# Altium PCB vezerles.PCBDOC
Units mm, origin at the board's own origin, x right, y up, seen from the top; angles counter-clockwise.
Board outline 152.4 x 101.6 mm, 2 copper layers (Top Layer, Bottom Layer); 54 components, 79 nets, 277 pads, 8 vias.
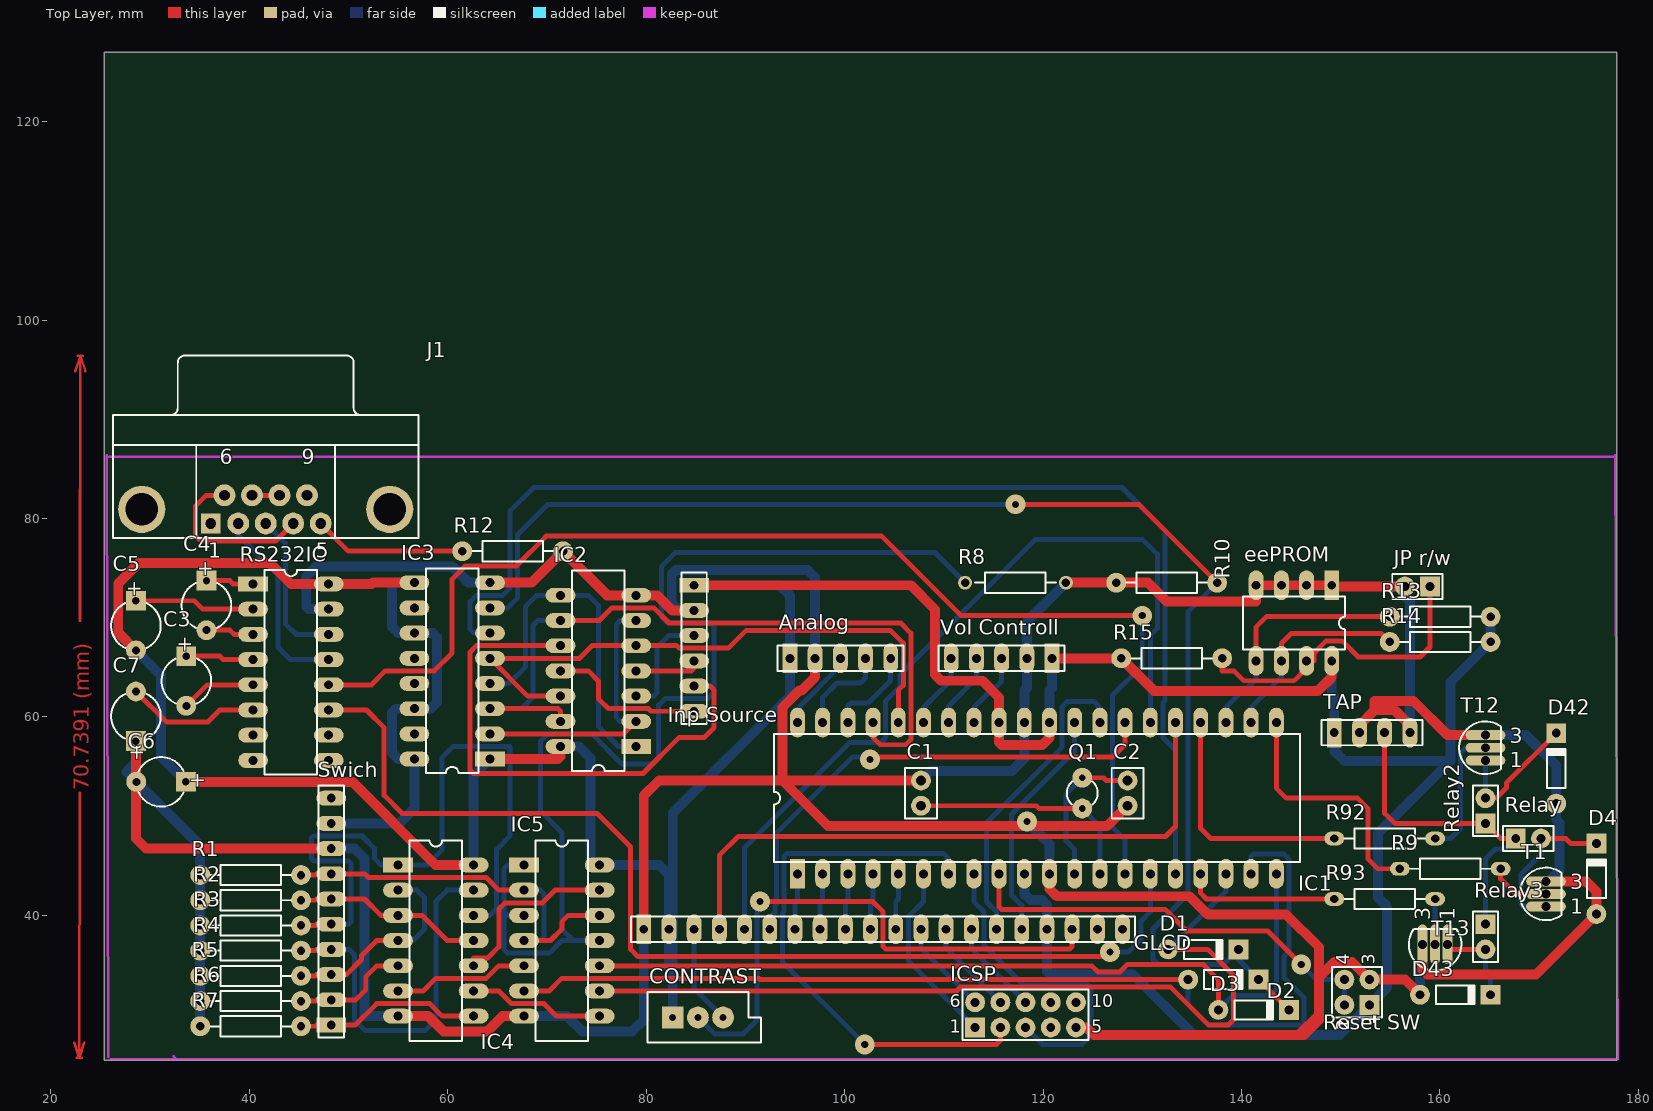
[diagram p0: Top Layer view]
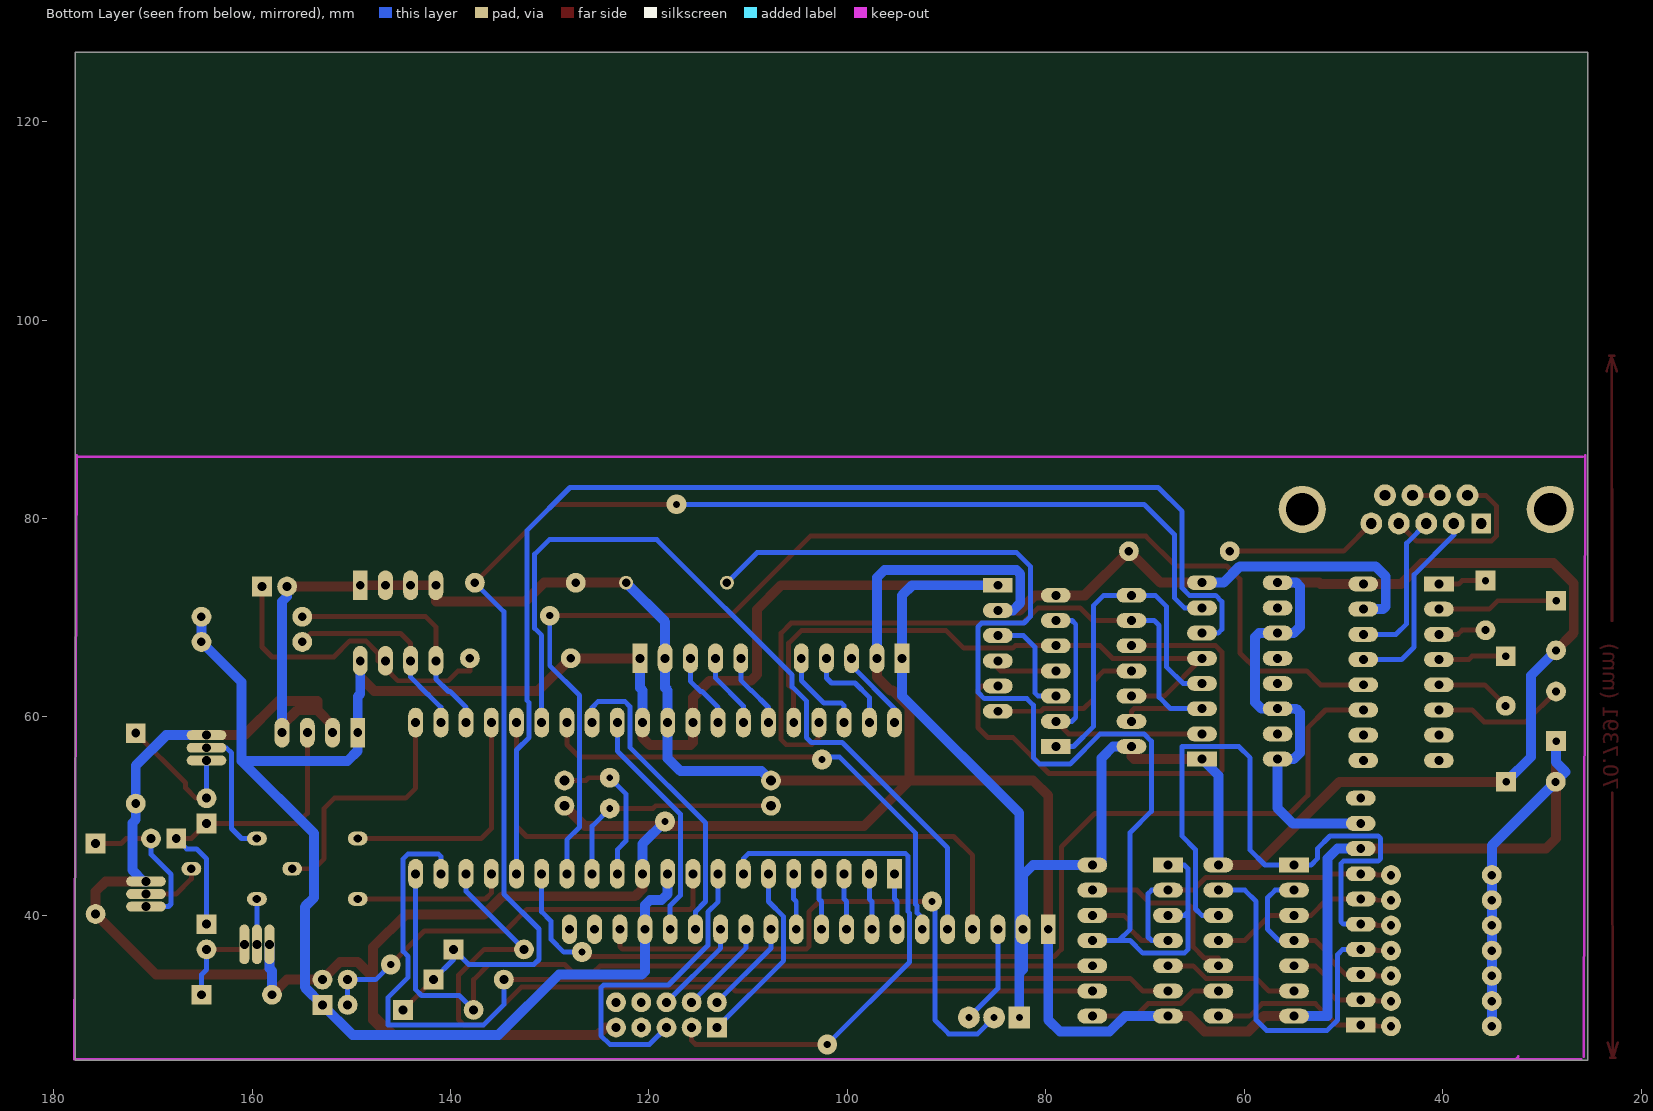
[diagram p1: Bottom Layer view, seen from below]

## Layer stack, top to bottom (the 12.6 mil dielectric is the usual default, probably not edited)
Top Layer: signal copper 0.0356
Dielectric: dielectric 0.32, FR-4, Dk 4.8
Bottom Layer: signal copper 0.0356

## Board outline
25.4,25.4 177.8,25.4 177.8,127 25.4,127

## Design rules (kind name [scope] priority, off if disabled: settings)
Clearance [All] p1: gap=0.254
ComponentClearance [All] p1: gap=0.254 collisioncheckmode=0
PolygonConnect [All] p1: connectstyle=Relief reliefconductorwidth=0.254 reliefentries=4 polygonreliefangle="90 Angle"
RoutingLayers [All] p1: top layer=Horizontal bottom layer=Vertical
RoutingTopology [All] p1: topology=Daisy_Balanced
RoutingVias [All] p1: holewidth=0.711 width=2 viastyle="Through Hole" minholewidth=0.711 minwidth=2 maxholewidth=0.711 maxwidth=2
SolderMaskExpansion [All] p1: expansion=0.102
TestPointUsage [All] p1: valid=0 allowmultiple=FALSE
Testpoint [All] p1: side=15 testpointundercomponent=TRUE minsize=1.016 maxsize=2.54 preferedsize=1.524 minholesize=0 maxholesize=1.016 preferedholesize=0.813 testpointgrid=0.025 style=1023 order=-539222988
Width Width_2 [InNet('GND')] p1: maxlimit=1 minlimit=0.254 preferedwidth=0.254 toplayer_minwidth=1 toplayer_prefwidth=1 bottomlayer_minwidth=1 bottomlayer_prefwidth=1 minimp=50.000000 maximp=50.000000 favimp=50.000000
Width Width_1 [InNet('VCC')] p2: maxlimit=1 minlimit=0.254 preferedwidth=0.254 toplayer_minwidth=1 toplayer_prefwidth=1 bottomlayer_minwidth=1 bottomlayer_prefwidth=1 minimp=50.000000 maximp=50.000000 favimp=50.000000
Width [All] p3: maxlimit=0.5 minlimit=0.254 preferedwidth=0.254 toplayer_minwidth=0.5 toplayer_prefwidth=0.5 bottomlayer_minwidth=0.5 bottomlayer_prefwidth=0.5 minimp=50.000000 maximp=50.000000 favimp=50.000000
15 further rules are at their usual default settings.

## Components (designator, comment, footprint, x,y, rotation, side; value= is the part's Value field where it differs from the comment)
Analog "Header 5" HDR1X5 94.488,65.913 r0 top
C1 "Cap" CAPR2.54-5.1X3.2 107.696,52.324 r270 top
C2 "Cap" CAPR2.54-5.1X3.2 128.524,52.324 r90 top
C3 "1uF" CAPPR5-5X5 33.655,63.627 r270 top
C4 "1uF" CAPPR5-5X5 35.687,71.247 r270 top
C5 "1uF" CAPPR5-5X5 28.575,69.215 r270 top
C6 "1uF" CAPPR5-5X5 31.115,53.467 r180 top
C7 "1uF" CAPPR5-5X5 28.575,60.071 r90 top
CONTRAST "RPot" VR5 85.217,29.718 r0 top
D1 "Diode 1N4148" DIO7.1-3.9x1.9 136.144,36.576 r0 top
D2 "Diode 1N4148" DIO7.1-3.9x1.9 138.176,33.528 r0 top
D3 "Diode 1N4148" DIO7.1-3.9x1.9 141.224,30.48 r0 top
D4 "Diode 1N4148" DIO7.1-3.9x1.9 175.768,43.688 r90 top
D42 "Diode 1N4148" DIO7.1-3.9x1.9 171.72,54.816 r90 top
D43 "Diode 1N4148" DIO7.1-3.9x1.9 161.544,32.004 r0 top
eePROM "M24C32BN1" PSDIP8A 145.288,69.469 r180 top
GLCD "Header 20" HDR1X20 79.756,38.608 r0 top
IC1 "ATmega8535-16PI" 40P6 119.38,51.816 r0 top
IC2 "HCF4081BEY" DIP14 75.184,64.643 r90 top
IC3 "HCF4009UBEY" DIP16 60.452,64.643 r90 top
IC4 "HCF4075BEY" DIP14 58.801,37.465 r270 top
IC5 "HCF4075BEY" DIP14 71.501,37.465 r270 top
ICSP "Header 5X2A" HDR2X5_CEN 113.157,28.702 r0 top
"Inp Source" "Header 6" HDR1X6 84.836,73.279 r270 top
J1 "DB-9" DSUB1.385-2H9 41.656,90.424 r0 top
"JP r/w" "Header 2" HDR1X2 159.004,73.152 r180 top
Q1 "XTAL" BCY-W2/D3.1 123.952,52.324 r180 top
R1 "Res2" AXIAL-0.4#1 40.132,44.069 r0 top
R2 "Res2" AXIAL-0.4#1 40.132,41.529 r0 top
R3 "Res2" AXIAL-0.4#1 40.132,38.989 r0 top
R4 "Res2" AXIAL-0.4#1 40.132,36.449 r0 top
R5 "Res2" AXIAL-0.4#1 40.132,33.909 r0 top
R6 "Res2" AXIAL-0.4#1 40.132,31.369 r0 top
R7 "Res2" AXIAL-0.4#1 40.132,28.829 r0 top
R8 "Res2" AXIAL-0.4#2 117.221,73.533 r180 top
R9 "Res2" AXIAL-0.4#3 161.036,44.704 r0 top
R10 "Res2" AXIAL-0.4#1 132.461,73.533 r0 top
R12 "10" AXIAL-0.4#1 66.548,76.708 r180 top
R13 "10" AXIAL-0.4#1 160.02,70.104 r0 top
R14 "10" AXIAL-0.4#1 160.02,67.564 r0 top
R15 "10" AXIAL-0.4#1 132.969,65.913 r180 top
R92 "Res2" AXIAL-0.4#3 154.432,47.752 r0 top
R93 "Res2" AXIAL-0.4#3 154.432,41.656 r0 top
Relay "Header 2" HDR1X2 167.64,47.752 r0 top
Relay2 "Header 2" HDR1X2 164.592,49.276 r90 top
Relay3 "Header 2" HDR1X2 164.592,39.116 r270 top
"Reset SW" "Header 2X2" HDR2X2 152.908,30.988 r90 top
RS232IC "MAX232" DIP16 44.196,64.516 r270 top
Swich "Header 10" HDR1X10 48.26,28.956 r90 top
T1 "NPN" BCY-W3 170.688,42.164 r0 top
T12 "NPN" BCY-W3 164.592,56.896 r0 top
T13 "NPN" BCY-W3 159.512,37.084 r90 top
TAP "Header 4" HDR1X4 149.352,58.42 r0 top
"Vol Controll" "Header 5" HDR1X5 120.904,65.913 r180 top

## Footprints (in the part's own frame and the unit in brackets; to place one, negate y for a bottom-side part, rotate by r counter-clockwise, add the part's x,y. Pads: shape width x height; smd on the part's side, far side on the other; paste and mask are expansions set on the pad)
40P6 [mm] "DIP; 40 Leads; Row Spacing 15.24 mm; Pitch 2.54 mm"
  rect 1.5x3 hole 0.9: 1(-24.13,-7.62)
  oval 1.5x3 hole 0.9: 2(-21.59,-7.62) 3(-19.05,-7.62) 4(-16.51,-7.62) 5(-13.97,-7.62) 6(-11.43,-7.62) 7(-8.89,-7.62) 8(-6.35,-7.62) 9(-3.81,-7.62) 10(-1.27,-7.62) 11(1.27,-7.62) 12(3.81,-7.62) 13(6.35,-7.62) 14(8.89,-7.62) 15(11.43,-7.62) 16(13.97,-7.62) 17(16.51,-7.62) 18(19.05,-7.62) 19(21.59,-7.62) 20(24.13,-7.62) 21(24.13,7.62) 22(21.59,7.62) 23(19.05,7.62) 24(16.51,7.62) 25(13.97,7.62) 26(11.43,7.62) 27(8.89,7.62) 28(6.35,7.62) 29(3.81,7.62) 30(1.27,7.62) 31(-1.27,7.62) 32(-3.81,7.62) 33(-6.35,7.62) 34(-8.89,7.62) 35(-11.43,7.62) 36(-13.97,7.62) 37(-16.51,7.62) 38(-19.05,7.62) 39(-21.59,7.62) 40(-24.13,7.62)
  silkscreen extent -26.5,-6.45 26.5,6.45
AXIAL-0.4#1 [mm]
  round 2 hole 0.85: 1(-5.08,0) 2(5.08,0)
  silkscreen extent -4.06,-1.02 4.06,1.02
AXIAL-0.4#2 [mm]
  round 1.4 hole 0.85: 1(-5.08,0) 2(5.08,0)
  silkscreen extent -4.06,-1.02 4.06,1.02
AXIAL-0.4#3 [mm]
  oval 2x1.4 hole 0.85: 1(-5.08,0) 2(5.08,0)
  silkscreen extent -4.06,-1.02 4.06,1.02
BCY-W2/D3.1 [mm]
  round 2 hole 0.7: 1(0,1.55) 2(0,-1.55)
  silkscreen extent -1.55,-1.19 1.55,1.17
BCY-W3 [mm]
  oval 4x1 hole 0.9: 1(0,-1.27) 2(0,0) 3(0,1.27)
  silkscreen extent -2.65,-2.65 1.55,2.65
CAPPR5-5X5 [mm]
  rect 2x2 hole 0.75: 1(-2.5,0)
  round 2 hole 0.8: 2(2.5,0)
  silkscreen extent -2.26,-2.5 2.27,2.5
CAPR2.54-5.1X3.2 [mm]
  round 2 hole 1: 1(-1.27,0) 2(1.27,0)
  silkscreen extent -2.55,-1.6 2.55,1.6
DIO7.1-3.9x1.9 [mm]
  round 2 hole 0.9: 1(-3.55,0)
  rect 2x2 hole 0.9: 2(3.55,0)
  silkscreen extent -1.95,-0.95 2.05,0.95
DIP14 [mm] "DIP; 14 Leads; Row Spacing 7.62 mm; Pitch 2.54 mm"
  rect 1.5x3 hole 0.9: 1(-7.62,-3.81)
  oval 1.5x3 hole 0.9: 2(-5.08,-3.81) 3(-2.54,-3.81) 4(0,-3.81) 5(2.54,-3.81) 6(5.08,-3.81) 7(7.62,-3.81) 8(7.62,3.81) 9(5.08,3.81) 10(2.54,3.81) 11(0,3.81) 12(-2.54,3.81) 13(-5.08,3.81) 14(-7.62,3.81)
  silkscreen extent -10.1,-2.65 10.1,2.65
DIP16 [mm] "DIP; 16 Leads; Row Spacing 7.62 mm; Pitch 2.54 mm"
  rect 1.5x3 hole 0.9: 1(-8.89,-3.81)
  oval 1.5x3 hole 0.9: 2(-6.35,-3.81) 3(-3.81,-3.81) 4(-1.27,-3.81) 5(1.27,-3.81) 6(3.81,-3.81) 7(6.35,-3.81) 8(8.89,-3.81) 9(8.89,3.81) 10(6.35,3.81) 11(3.81,3.81) 12(1.27,3.81) 13(-1.27,3.81) 14(-3.81,3.81) 15(-6.35,3.81) 16(-8.89,3.81)
  silkscreen extent -10.3,-2.65 10.3,2.65
DSUB1.385-2H9 [mm] "Connector; D Subminiature; 9 Position; Right Angle; Pitch 1.385 mm"
  rect 2x2 hole 1.09: 1(-5.54,-10.92)
  round 2.2 hole 1.09: 2(-2.77,-10.92) 3(0,-10.92) 4(2.77,-10.92) 5(5.54,-10.92) 6(-4.155,-8.08) 7(-1.385,-8.08) 8(1.385,-8.08) 9(4.155,-8.08)
  round 4.76 hole 3.26: 10(-12.495,-9.5) 11(12.495,-9.5)
  silkscreen extent -15.4,-12.4 15.4,6
HDR1X2 [mm] "Connector; Header; 2 Position"
  rect 2x2 hole 0.9: 1(0,0)
  round 2 hole 0.9: 2(2.54,0)
  silkscreen extent -1.27,-1.27 3.81,1.27
HDR1X4 [mm] "Connector; Header; 4 Position"
  rect 1.5x3 hole 0.9: 1(0,0)
  oval 1.5x3 hole 0.9: 2(2.54,0) 3(5.08,0) 4(7.62,0)
  silkscreen extent -1.27,-1.27 8.89,1.27
HDR1X5 [mm] "Connector; Header; 5 Position"
  rect 1.5x3 hole 0.9: 1(0,0)
  oval 1.5x3 hole 0.9: 2(2.54,0) 3(5.08,0) 4(7.62,0) 5(10.16,0)
  silkscreen extent -1.27,-1.27 11.43,1.27
HDR1X6 [mm] "Connector; Header; 6 Position"
  rect 1.5x3 hole 0.9: 1(0,0)
  oval 1.5x3 hole 0.9: 2(2.54,0) 3(5.08,0) 4(7.62,0) 5(10.16,0) 6(12.7,0)
  silkscreen extent -1.27,-1.27 13.97,1.27
HDR1X10 [mm] "Connector; Header; 10 Position"
  rect 1.5x3 hole 0.9: 1(0,0)
  oval 1.5x3 hole 0.9: 2(2.54,0) 3(5.08,0) 4(7.62,0) 5(10.16,0) 6(12.7,0) 7(15.24,0) 8(17.78,0) 9(20.32,0) 10(22.86,0)
  silkscreen extent -1.27,-1.27 24.13,1.27
HDR1X20 [mm] "Connector; Header; 20 Position"
  rect 1.5x3 hole 0.9 paste+0: 1(0,0)
  oval 1.5x3 hole 0.9 paste+0: 2(2.54,0) 3(5.08,0) 4(7.62,0) 5(10.16,0) 6(12.7,0) 7(15.24,0) 8(17.78,0) 9(20.32,0) 10(22.86,0) 11(25.4,0) 12(27.94,0) 13(30.48,0) 14(33.02,0) 15(35.56,0) 16(38.1,0) 17(40.64,0) 18(43.18,0) 19(45.72,0) 20(48.26,0)
  silkscreen extent -1.27,-1.27 49.53,1.27
HDR2X2 [mm] "Connector; Header; 2x2 Position"
  rect 2x2 hole 0.9: 1(0,0)
  round 2 hole 0.9: 2(0,2.54) 3(2.54,0) 4(2.54,2.54)
  silkscreen extent -1.27,-1.27 3.81,3.81
HDR2X5_CEN [mm] "Connector; Header; 5x2 Position"
  rect 2x2 hole 0.9: 1(0,0)
  round 2 hole 0.9: 2(2.54,0) 3(5.08,0) 4(7.62,0) 5(10.16,0) 6(0,2.54) 7(2.54,2.54) 8(5.08,2.54) 9(7.62,2.54) 10(10.16,2.54)
  silkscreen extent -1.27,-1.27 11.43,3.81
PSDIP8A [mm] "DIP; 8 Leads; Row Spacing 7.62 mm; Pitch 2.54 mm"
  rect 1.5x3 hole 0.9: 1(-3.81,-3.81)
  oval 1.5x3 hole 0.9: 2(-1.27,-3.81) 3(1.27,-3.81) 4(3.81,-3.81) 5(3.81,3.81) 6(1.27,3.81) 7(-1.27,3.81) 8(-3.81,3.81)
  silkscreen extent -5.15,-2.65 5.15,2.65
VR5 [mm]
  rect 2.2x2.2 hole 0.7: 1(-2.54,0)
  round 2.2 hole 0.7: 2(0,0) 3(2.54,0)
  silkscreen extent -5.08,-2.54 6.35,2.54

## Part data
Analog "Vol Controll": "Header, 5-Pin"
C1 C2: "Capacitor"
C3 C4 C5 C6 C7: library part CPOL, "Elektrolit kondenzátor"
CONTRAST: "Potentiometer"
D1 D2 D3 D4 D42 D43: "High Conductance Fast Diode"
eePROM: "32 Kbit Serial I²C Bus EEPROM"
GLCD: "Header, 20-Pin"
IC1: "8-Bit AVR Microcontroller with 8K Bytes of In-System Programmable Flash Memory"
IC2: "Quad 2-Input AND Gate"
IC3: "Hex Buffer/Converter"
IC4 IC5: "Triple 3-Input OR Gate"
ICSP: "Header, 5-Pin, Dual row"
"Inp Source": "Header, 6-Pin"
J1: library part DB9
"JP r/w" Relay Relay2 Relay3: "Header, 2-Pin"
Q1: "Crystal Oscillator"
R1 R2 R3 R4 R5 R6 R7 R8 R9 R10 R92 R93: "Resistor"
R12 R13 R14 R15: library part Res2, "Resistor"
"Reset SW": "Header, 2-Pin, Dual row"
RS232IC: "DUAL EIA-232 DRIVER/RECEIVER"
Swich: "Header, 10-Pin"
T1 T12 T13: "NPN Bipolar Transistor"
TAP: "Header, 4-Pin"

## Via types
v1: diameter 2, hole 0.711, Top Layer to Bottom Layer, 8 vias

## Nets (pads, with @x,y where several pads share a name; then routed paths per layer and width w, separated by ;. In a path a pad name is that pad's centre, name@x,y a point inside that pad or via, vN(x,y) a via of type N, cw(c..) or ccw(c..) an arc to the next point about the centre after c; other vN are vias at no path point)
12: Relay2.1 Relay3.1 Relay.1 TAP.3 | length 32.9
  Top Layer w0.5: TAP.3 154.432,50.292 155.448,49.276 Relay2.1 166.116,47.752 Relay.1
  Bottom Layer w0.5: Relay3.1 164.592,45.695 165.608,46.711 166.599,46.711 Relay.1
+10V: C5.1 RS232IC.2 | length 12.2
  Top Layer w0.5: C5.1 34.468,71.715 35.317,70.866 RS232IC.2
-10V: C7.2 RS232IC.6 | length 13.6
  Top Layer w0.5: C7.2 31.634,59.512 35.839,59.512 37.033,60.706 RS232IC.6
CS1: GLCD.15 IC1.28 | length 31.8
  Bottom Layer w0.5: GLCD.15 115.316,40.386 114.3,41.402 114.3,49.327 121.92,56.947 121.92,61.062 122.428,61.57 125.12,61.57 125.73,60.96 IC1.28
CS2: GLCD.16 IC1.29 | length 23.9
  Bottom Layer w0.5: GLCD.16 117.856,40.996 116.84,42.012 116.84,50.216 123.19,56.566 IC1.29
D0: GLCD.7 IC1.1 | length 5.7
  Bottom Layer w0.5: GLCD.7 94.996,41.402 95.25,41.656 IC1.1
D1: GLCD.8 IC1.2 | length 5.7
  Bottom Layer w0.5: GLCD.8 97.536,41.402 97.79,41.656 IC1.2
D2: GLCD.9 IC1.3 | length 5.7
  Bottom Layer w0.5: GLCD.9 100.076,41.402 100.33,41.656 IC1.3
D3: GLCD.10 IC1.4 | length 5.7
  Bottom Layer w0.5: GLCD.10 102.616,41.402 102.87,41.656 IC1.4
D4: GLCD.11 IC1.5 | length 5.7
  Bottom Layer w0.5: GLCD.11 105.156,41.402 105.41,41.656 IC1.5
D5: GLCD.12 ICSP.6 | length 9.6
  Bottom Layer w0.5: GLCD.12 107.696,36.703 ICSP.6
D6: GLCD.13 ICSP.7 | length 9.6
  Bottom Layer w0.5: GLCD.13 110.236,36.703 ICSP.7
D7: GLCD.14 ICSP.8 | length 9.6
  Bottom Layer w0.5: GLCD.14 112.776,36.703 ICSP.8
E: GLCD.6 IC1.27 | length 51.2
  Top Layer w0.5: v1(102.565,55.702) 102.819,55.956 127,55.956 128.27,57.226 IC1.27
  Bottom Layer w0.5: GLCD.6 92.456,39.751 92.964,40.259 92.964,40.97 93.116,41.123 93.116,48.285 100.787,55.956 102.311,55.956 v1(102.565,55.702)
GND: "Inp Source.2" "JP r/w.2" "Reset SW.3" "Vol Controll.2" Analog.2 C1.1 C2.1 C6.2 C7.1 D4.1 D42.1 D43.1 eePROM.1 eePROM.2 eePROM.3 eePROM.4 GLCD.1 IC1.11 IC1.31 IC2.7 IC3.8 IC4.7 IC5.7 ICSP.5 R1.1 R2.1 R3.1 R4.1 R5.1 R6.1 R7.1 R8.1 R10.1 R12.1 RS232IC.15 Swich.8 T1.3 T12.3 T13.3 TAP.2 TAP.4 | length 539.1
  Top Layer w1: C7.1 28.575,53.467 28.575,47.752 29.591,46.736 Swich.8 ; IC4.7 58.039,29.845 59.563,28.321 64.008,28.321 65.532,29.845 IC5.7 ; IC3.8 68.453,73.533 R12.1 76.073,72.263 IC2.7 81.102,72.263 82.626,70.739 84.836,70.739 ; GLCD.1 79.756,52.07 81.28,53.594 93.726,53.594 ; Analog.2 97.028,64.008 95.682,62.662 95.428,62.662 93.726,60.96 93.726,53.594 ; C1.1 93.726,53.594 ; v1(118.389,49.479) v1@118.872,48.997 ; IC1.11 120.65,42.672 121.387,41.935 134.772,41.935 136.601,40.107 144.501,40.107 147.803,36.805 147.803,33.757 ; R8.1 R10.1 130.581,73.533 132.461,71.653 141.478,71.653 eePROM.4 eePROM.3 eePROM.2 eePROM.1 149.098,73.152 156.464,73.152 ; ICSP.5 124.384,28.702 125.12,27.965 145.796,27.965 ; C2.1 126.467,48.997 v1@118.872,48.997 ; TAP.2 151.892,59.157 153.416,60.681 ; TAP.4 156.972,59.157 155.448,60.681 153.416,60.681 ; D43.1 156.47,33.528 152.908,33.528 151.13,35.306 149.352,35.306 147.803,33.757 ; T13.3 158.242,34.544 158.75,34.036 169.666,34.036 D4.1 175.768,42.418 174.752,43.434 T1.3 ; T12.3 160.782,58.166 157.328,61.62 153.416,61.62 153.416,60.681 ; 93.726,53.594 98.323,48.997 118.389,48.997 v1@118.872,48.997 ; 145.796,27.965 147.803,29.972 ; 145.796,27.965 146.304,27.965 147.803,29.464 147.803,29.972 ; 147.803,29.972 147.803,33.757
  Bottom Layer w1: C7.1 28.575,55.437 27.61,54.472 C6.2 35.052,47.03 R1.1 R2.1 R3.1 R4.1 R5.1 R6.1 R7.1 ; RS232IC.15 45.999,70.866 45.745,71.12 45.745,74.168 46.761,75.184 60.452,75.184 62.103,73.533 IC3.8 ; Swich.8 50.597,46.736 51.613,45.72 51.613,29.87 51.638,29.845 IC4.7 ; IC5.7 72.034,29.845 73.584,28.296 78.588,28.296 79.756,29.464 GLCD.1 ; 84.836,70.739 83.312,70.739 82.575,71.476 82.575,74.422 82.956,74.803 96.266,74.803 97.028,74.041 Analog.2 ; C1.1 108.661,54.559 116.84,54.559 118.11,55.829 IC1.31 118.11,62.687 118.364,62.941 118.364,65.913 118.364,69.596 R8.1 ; v1(118.389,49.479) 120.65,47.219 IC1.11 ; 156.464,73.152 156.464,72.136 156.972,71.628 TAP.4 ; D43.1 157.994,34.417 158.242,34.665 T13.3 ; T12.3 168.656,58.166 171.72,55.102 D42.1 171.72,49.666 172.06,49.327 172.06,44.552 170.942,43.434 T1.3
NetAnalog_3: Analog.3 IC1.40 | length 8.3
  Bottom Layer w0.5: IC1.40 95.25,60.833 99.568,65.151 Analog.3
NetAnalog_4: Analog.4 IC1.39 | length 9.6
  Bottom Layer w0.5: IC1.39 97.79,61.976 99.238,63.424 101.6,63.424 102.108,63.932 Analog.4
NetAnalog_5: Analog.5 IC1.38 | length 9.3
  Bottom Layer w0.5: IC1.38 100.33,61.138 100.584,61.392 102.362,61.392 104.648,63.678 Analog.5
NetC1_2: C1.2 IC1.13 Q1.1 | length 23.7
  Top Layer w0.5: C1.2 119.329,51.054 119.609,50.774 Q1.1
  Bottom Layer w0.5: Q1.1 125.73,48.996 IC1.13
NetC2_2: C2.2 IC1.12 Q1.2 | length 15.4
  Top Layer w0.5: Q1.2 126.086,53.874 126.366,53.594 C2.2
  Bottom Layer w0.5: IC1.12 123.19,46.634 122.326,47.498 122.326,52.248 Q1.2
NetC3_1: C3.1 RS232IC.4 | length 6.9
  Top Layer w0.5: C3.1 37.033,66.127 37.374,65.786 RS232IC.4
NetC3_2: C3.2 RS232IC.5 | length 7.6
  Top Layer w0.5: C3.2 35.774,63.246 RS232IC.5
NetC4_1: C4.1 RS232IC.1 | length 4.8
  Top Layer w0.5: C4.1 38.049,73.747 38.39,73.406 RS232IC.1
NetC4_2: C4.2 RS232IC.3 | length 4.9
  Top Layer w0.5: C4.2 38.049,68.747 38.47,68.326 RS232IC.3
NetD1_1: D1.1 IC1.18 IC5.9 | length 88
  Top Layer w0.5: IC5.9 111.277,32.385 111.658,32.766 132.862,32.766 136.652,28.976 138.684,28.976 139.192,29.484 139.192,33.985 136.601,36.576 D1.1
  Bottom Layer w0.5: D1.1 138.43,42.412 IC1.18
NetD1_2: D1.2 D2.2 D3.2 IC3.7 R10.2 | length 142.9
  Top Layer w0.5: v1(117.221,81.432) 129.642,81.432 R10.2 ; D2.2 141.726,33.509 144.755,30.48 D3.2
  Bottom Layer w0.5: IC3.7 66.04,70.993 67.056,72.009 67.056,78.384 70.104,81.432 v1(117.221,81.432) ; R10.2 134.62,70.612 134.62,42.164 131.089,38.633 131.089,35.56 131.597,35.052 138.17,35.052 D1.2 139.694,35.56 D2.2
NetD2_1: D2.1 IC1.19 IC5.6 | length 106.2
  Top Layer w0.5: IC5.6 70.231,32.385 71.501,33.655 91.364,33.655 91.491,33.528 D2.1
  Bottom Layer w0.5: D2.1 134.626,31.002 136.652,28.976 146.279,28.976 146.279,31.75 144.272,33.757 144.272,35.865 144.78,36.373 144.78,45.695 144.272,46.203 141.224,46.203 140.97,45.949 IC1.19
NetD3_1: D3.1 IC1.20 IC5.10 | length 85
  Top Layer w0.5: IC5.10 124.917,34.925 125.552,34.29 127.737,34.29 128.499,35.052 136.15,35.052 137.674,33.528 D3.1
  Bottom Layer w0.5: D3.1 139.122,31.928 142.926,31.928 143.51,32.512 IC1.20
NetD4_2: D4.2 Relay.2 T1.1 | length 15.9
  Top Layer w0.5: Relay.2 172.695,47.752 173.209,47.238 D4.2
  Bottom Layer w0.5: Relay.2 170.18,46.152 168.173,44.145 168.173,41.148 168.427,40.894 T1.1
NetD42_2: D42.2 Relay2.2 T12.1 | length 13.9
  Top Layer w0.5: Relay2.2 165.678,51.816 166.7,52.838 166.7,53.346 D42.2
  Bottom Layer w0.5: Relay2.2 T12.1
NetD43_2: D43.2 Relay3.2 T13.1 | length 9.1
  Top Layer w0.5: T13.1 160.782,36.576 Relay3.2
  Bottom Layer w0.5: Relay3.2 164.592,34.538 165.094,34.036 D43.2
Neteeprom_5: eePROM.5 IC1.23 R13.1 | length 24.9
  Top Layer w0.5: eePROM.5 141.478,69.088 142.494,70.104 R13.1
  Bottom Layer w0.5: IC1.23 138.43,60.96 140.03,62.56 140.208,62.56 141.478,63.83 eePROM.5
Neteeprom_6: eePROM.6 IC1.22 R14.1 | length 21
  Top Layer w0.5: eePROM.6 144.018,67.412 145.034,68.428 154.076,68.428 R14.1
  Bottom Layer w0.5: IC1.22 140.97,60.985 142.24,62.255 142.265,62.255 144.018,64.008 eePROM.6
Neteeprom_7: "JP r/w.1" eePROM.7 R15.1 | length 32.4
  Top Layer w0.5: R15.1 138.049,64.618 139.271,64.618 140.236,63.652 145.313,63.652 146.558,64.897 eePROM.7 147.32,65.659 147.32,66.446 148.539,67.666 150.139,67.666 151.765,66.04 157.988,66.04 159.004,67.056 159.004,73.152
NetIC1_9: "Reset SW.2" "Reset SW.4" IC1.9 | length 43.7
  Top Layer w0.5: IC1.9 115.57,40.869 115.824,40.615 132.309,40.615 134.493,38.43 142.646,38.43 v1(146.025,35.052)
  Bottom Layer w0.5: v1(146.025,35.052) 147.549,33.528 150.368,33.528 150.368,30.988
NetIC1_16: IC1.16 IC3.6 | length 121.3
  Bottom Layer w0.5: IC3.6 62.636,68.453 62.255,68.834 62.255,71.628 62.89,72.263 65.532,72.263 66.269,73 66.269,80.721 68.682,83.134 127.965,83.134 132.283,78.816 132.283,61.646 132.08,61.443 132.08,57.937 133.35,56.667 IC1.16
NetIC1_17: IC1.17 R93.1 | length 15.7
  Top Layer w0.5: IC1.17 135.89,42.24 136.474,41.656 R93.1
NetIC1_21: IC1.21 R9.1 | length 25.4
  Top Layer w0.5: IC1.21 143.51,52.832 144.526,51.816 151.714,51.816 152.73,50.8 152.73,45.72 153.746,44.704 R9.1
NetIC1_24: IC1.24 R92.1 | length 24.6
  Top Layer w0.5: IC1.24 135.89,48.768 136.906,47.752 R92.1
NetIC1_33: "Vol Controll.3" IC1.33 | length 7.7
  Bottom Layer w0.5: IC1.33 113.03,60.96 114.656,62.586 114.808,62.586 115.824,63.602 115.824,65.913
NetIC1_34: "Vol Controll.4" IC1.34 | length 7.6
  Bottom Layer w0.5: IC1.34 110.49,61.112 113.284,63.906 113.284,65.913
NetIC1_35: "Vol Controll.5" IC1.35 | length 7.7
  Bottom Layer w0.5: IC1.35 107.95,60.96 109.677,62.687 109.728,62.687 110.744,63.703 110.744,65.913
NetIC1_36: IC1.36 IC2.5 IC2.12 IC3.5 | length 60.5
  Top Layer w0.5: IC2.12 68.072,62.103 IC3.5 73.279,65.913 74.549,67.183 IC2.5 83.083,67.183 83.337,66.929 88.265,66.929 90.043,68.707 104.648,68.707 105.918,67.437 105.918,63.195 105.41,62.687 IC1.36
NetIC1_37: IC1.37 IC2.9 IC2.13 IC3.3 | length 76.7
  Top Layer w0.5: IC3.3 71.12,60.833 71.374,60.579 IC2.13 ; IC2.9 75.286,69.723 76.556,70.993 80.772,70.993 82.296,69.469 105.664,69.469 106.68,68.453 106.68,57.709 106.172,57.201 103.581,57.201 102.87,57.912 IC1.37
  Bottom Layer w0.5: IC3.3 67.437,60.833 68.58,61.976 68.58,69.215 69.088,69.723 IC2.9
NetIC2_1: IC2.1 IC2.8 IC3.4 | length 35.4
  Bottom Layer w0.5: IC3.4 66.167,63.373 67.818,65.024 67.818,71.12 68.961,72.263 IC2.8 74.168,72.263 75.184,71.247 75.184,59.055 77.216,57.023 IC2.1
NetIC2_2: IC2.2 IC2.6 IC3.2 | length 29
  Top Layer w0.5: IC3.2 77.724,58.293 IC2.2
  Bottom Layer w0.5: IC2.2 77.368,59.563 76.987,59.944 76.987,69.342 77.368,69.723 IC2.6
NetIC2_3: "Inp Source.3" IC2.3 | length 11.1
  Bottom Layer w0.5: IC2.3 80.772,62.103 81.102,62.433 81.102,67.056 82.245,68.199 84.836,68.199
NetIC2_4: "Inp Source.4" IC2.4 | length 6.7
  Top Layer w0.5: IC2.4 84.582,64.643 84.836,64.897 84.836,65.659
NetIC2_10: "Inp Source.5" IC2.10 | length 53.9
  Top Layer w0.5: IC2.10 62.89,67.183 62.255,66.548 62.255,54.61 62.56,54.305 79.68,54.305 83.287,57.912 85.827,57.912 86.843,58.928 86.843,62.738 86.462,63.119 84.836,63.119
NetIC2_11: "Inp Source.6" IC2.11 | length 16.2
  Top Layer w0.5: IC2.11 74.168,64.643 75.184,63.627 75.184,61.849 76.2,60.833 80.239,60.833 80.493,60.579 84.836,60.579
NetIC4_1: IC4.1 IC4.12 R3.2 Swich.5 | length 69.1
  Top Layer w0.5: R3.2 46.66,38.989 46.787,39.116 Swich.5
  Bottom Layer w0.5: Swich.5 50.013,39.116 50.267,39.37 50.267,45.212 50.013,45.466 46.507,45.466 46.253,45.72 46.253,47.752 46.507,48.006 51.359,48.006 52.629,46.736 52.629,45.72 53.264,45.085 IC4.1 57.912,45.085 59.411,46.584 59.411,55.88 60.554,57.023 66.269,57.023 66.269,47.981 64.922,46.634 64.922,40.64 64.287,40.005 IC4.12
NetIC4_2: IC4.2 IC4.4 R5.2 Swich.3 | length 20.8
  Top Layer w0.5: R5.2 46.66,33.909 46.787,34.036 Swich.3 49.784,34.036 51.308,35.56 51.308,35.941 52.832,37.465 IC4.4
  Bottom Layer w0.5: IC4.4 56.515,37.465 57.658,38.608 57.658,41.783 56.896,42.545 IC4.2
NetIC4_3: IC4.3 IC4.11 R2.2 Swich.6 | length 19.2
  Top Layer w0.5: R2.2 46.66,41.529 46.787,41.656 Swich.6 51.613,41.656 53.264,40.005 IC4.3 57.404,40.005 59.944,37.465 IC4.11
NetIC4_5: IC4.5 R6.2 Swich.2 | length 12
  Top Layer w0.5: R6.2 46.66,31.369 46.787,31.496 Swich.2 50.724,31.496 51.74,32.512 51.74,33.833 52.832,34.925 IC4.5
NetIC4_6: IC4.6 IC5.5 | length 13.8
  Top Layer w0.5: IC4.6 57.531,32.385 58.801,33.655 63.881,33.655 65.151,34.925 IC5.5
NetIC4_8: IC4.8 R7.2 Swich.1 | length 18.9
  Top Layer w0.5: R7.2 46.66,28.829 46.787,28.956 Swich.1 50.673,28.956 52.832,31.115 58.191,31.115 59.461,29.845 IC4.8
NetIC4_9: IC4.9 IC5.8 | length 13.8
  Top Layer w0.5: IC4.9 65.151,32.385 66.421,31.115 69.698,31.115 70.968,29.845 IC5.8
NetIC4_10: IC4.10 IC5.13 | length 18.5
  Top Layer w0.5: IC4.10 62.611,35.687 64.008,35.687 65.151,36.83 65.151,40.64 65.786,41.275 69.545,41.275 70.815,42.545 IC5.13
NetIC4_13: IC4.13 R4.2 Swich.4 | length 37.5
  Top Layer w0.5: R4.2 46.66,36.449 46.787,36.576 Swich.4
  Bottom Layer w0.5: Swich.4 50.089,36.576 50.597,36.068 50.597,29.464 51.638,28.423 57.76,28.423 58.801,29.464 58.801,41.402 59.944,42.545 IC4.13
NetIC5_1: IC5.1 IC5.3 IC5.11 R8.2 | length 119.2
  Bottom Layer w0.5: IC5.3 66.04,40.005 65.684,40.361 ; IC5.1 66.04,45.085 65.684,44.729 65.684,40.361 ; IC5.11 72.644,37.465 ; R8.2 109.118,76.556 82.931,76.556 81.559,75.184 81.559,70.104 82.194,69.469 86.462,69.469 86.843,69.088 86.843,62.484 86.208,61.849 81.915,61.849 81.255,61.189 81.255,55.88 80.62,55.245 77.572,55.245 74.524,58.293 70.104,58.293 69.367,57.556 69.367,50.495 71.501,48.362 71.501,38.608 72.644,37.465 ; 65.684,40.361 65.684,36.551 66.04,36.195 70.231,36.195 71.501,37.465 72.644,37.465
NetIC5_2: IC5.2 IC5.4 IC5.12 R1.2 Swich.7 | length 41
  Top Layer w0.5: R1.2 46.66,44.069 46.787,44.196 Swich.7 51.638,44.196 52.019,43.815 63.881,43.815 65.151,42.545 IC5.2 ; IC5.4 70.358,37.465 71.501,38.608 71.501,39.37 72.136,40.005 IC5.12
  Bottom Layer w0.5: IC5.4 69.342,37.465 69.698,37.821 69.698,42.189 69.342,42.545 IC5.2
NetJ1_2: J1.2 RS232IC.13 | length 19.8
  Bottom Layer w0.5: J1.2 38.886,78.335 42.875,74.346 42.875,67.056 44.145,65.786 RS232IC.13
NetJ1_3: J1.3 RS232IC.14 | length 15.7
  Bottom Layer w0.5: J1.3 43.637,77.523 43.637,69.393 44.704,68.326 RS232IC.14
NetJ1_4: J1.4 J1.6 | length 17.2
  Top Layer w0.5: J1.6 35.659,82.344 34.595,81.28 34.595,78.232 35.103,77.724 42.646,77.724 J1.4
NetJ1_5: J1.5 R12.2 | length 15.4
  Top Layer w0.5: J1.5 49.992,76.708 R12.2
NetJ1_7: J1.7 J1.8 | length 2.8
  Top Layer w0.5: J1.7 J1.8
NetR9_2: R9.2 T1.2 | length 6.2
  Top Layer w0.5: R9.2 166.116,43.688 167.64,42.164 T1.2
NetR92_2: R92.2 T12.2 | length 13.3
  Bottom Layer w0.5: R92.2 161.061,47.752 162.077,48.768 162.077,56.388 162.585,56.896 T12.2
NetR93_2: R93.2 T13.2 | length 4.6
  Bottom Layer w0.5: T13.2 R93.2
PB5: IC1.6 ICSP.1 | length 18.9
  Bottom Layer w0.5: IC1.6 107.95,41.402 106.426,39.878 106.426,35.433 ICSP.1
PB6: IC1.7 ICSP.2 | length 56.1
  Top Layer w0.5: v1(102.032,27) 115.316,27 115.697,27.381 ICSP.2
  Bottom Layer w0.5: v1(102.032,27) 93.726,35.306 93.726,40.234 93.878,40.386 93.878,45.974 94.158,46.253 109.957,46.253 110.49,45.72 IC1.7
PB7: IC1.8 ICSP.3 | length 32.7
  Bottom Layer w0.5: IC1.8 113.03,41.377 114.046,40.361 114.046,36.982 118.034,32.995 124.562,32.995 124.841,32.715 124.841,27.889 123.952,27 119.939,27 ICSP.3
RS: GLCD.4 IC1.25 | length 65.1
  Top Layer w0.5: GLCD.4 87.376,46.05 89.281,47.955 132.334,47.955 133.35,48.971 IC1.25
RW: GLCD.5 IC1.26 | length 83.4
  Bottom Layer w0.5: GLCD.5 89.916,46.812 100.533,57.429 103.632,57.429 104.14,57.937 104.14,61.62 105.562,63.043 105.562,64.237 119.202,77.876 130.048,77.876 131.521,76.403 131.521,68.936 130.81,68.224 IC1.26
RXD: IC1.14 RS232IC.12 | length 123.7
  Top Layer w0.5: RS232IC.12 52.324,63.246 53.721,64.643 58.649,64.643 60.452,66.446 60.452,73.889 61.773,75.209 66.904,75.209 69.926,78.232 103.734,78.232 111.76,70.206 v1(129.997,70.206)
  Bottom Layer w0.5: IC1.14 128.27,47.625 127,48.895 127,62.179 129.997,65.176 v1(129.997,70.206)
TXD: IC1.15 RS232IC.11 | length 109.9
  Top Layer w0.5: RS232IC.11 51.816,60.706 53.594,58.928 53.594,52.095 55.423,50.267 75.057,50.267 78.435,46.888 78.435,36.576 79.172,35.839 126.289,35.839 v1(126.746,36.297)
  Bottom Layer w0.5: v1(126.746,36.297) 128.575,36.297 129.87,37.592 129.87,39.421 130.81,40.361 IC1.15
V0: CONTRAST.3 GLCD.3 | length 10.1
  Bottom Layer w0.5: GLCD.3 84.836,32.639 CONTRAST.3
VCC: "Inp Source.1" "Reset SW.1" "Vol Controll.1" Analog.1 C5.2 C6.1 CONTRAST.1 eePROM.8 GLCD.2 GLCD.17 IC1.10 IC1.30 IC1.32 IC2.14 IC3.1 IC3.9 IC3.11 IC3.14 IC3.16 IC4.14 IC5.14 R13.2 R14.2 R15.2 RS232IC.16 Swich.9 TAP.1 | length 443.5
  Top Layer w1: C5.2 26.797,68.493 26.797,73.457 28.854,75.514 42.088,75.514 44.196,73.406 RS232IC.16 52.324,73.406 52.451,73.533 IC3.9 ; C6.1 50.394,53.467 58.776,45.085 IC4.14 ; IC3.1 71.12,55.753 71.374,56.007 IC2.14 ; 84.836,73.279 106.68,73.279 109.118,70.841 109.118,64.262 109.728,63.652 113.894,63.652 115.57,61.976 IC1.32 115.57,57.429 115.824,57.175 119.913,57.175 120.65,57.912 IC1.30 ; 120.904,65.913 R15.2 131.166,62.636 147.726,62.636 149.098,64.008 eePROM.8
  Bottom Layer w1: C5.2 31.115,64.175 31.115,55.967 C6.1 ; Swich.9 55.118,49.276 56.642,50.8 IC3.16 55.016,55.753 54.381,56.388 54.381,60.452 54.762,60.833 IC3.14 58.268,60.833 58.903,61.468 58.903,68.072 58.522,68.453 IC3.11 55.016,68.453 54.381,69.088 54.381,73.152 54.762,73.533 IC3.9 ; IC4.14 62.611,54.102 IC3.1 ; IC2.14 73.228,57.023 74.371,55.88 74.371,45.085 IC5.14 81.28,45.085 82.296,44.069 GLCD.2 82.296,34.544 82.677,34.163 ; CONTRAST.1 82.677,34.163 ; 84.836,73.279 93.472,73.279 94.488,72.263 Analog.1 94.488,62.128 82.677,50.317 82.677,38.608 82.677,34.163 ; IC1.10 118.11,42.164 118.72,41.554 119.888,41.554 120.396,41.046 GLCD.17 120.396,34.366 120.726,34.036 129.083,34.036 135.153,27.965 149.885,27.965 152.908,30.988 154.686,32.766 154.686,40.869 153.772,41.783 153.772,48.285 161.061,55.575 ; IC1.30 120.65,62.687 120.904,62.941 120.904,65.913 ; eePROM.8 149.098,62.306 149.352,62.052 TAP.1 149.352,56.591 150.368,55.575 161.061,55.575 ; R13.2 R14.2 161.061,63.525 161.061,55.575
VOUT: CONTRAST.2 GLCD.18 | length 56.7
  Top Layer w0.5: v1(91.465,41.402) 102.845,41.402 103.886,40.361 103.886,36.855 104.14,36.601 122.682,36.601 122.936,36.855 GLCD.18
  Bottom Layer w0.5: CONTRAST.2 86.868,28.067 89.789,28.067 91.186,29.464 91.186,41.123 v1(91.465,41.402)
pads on no net: GLCD.19 GLCD.20 IC3.10 IC3.12 IC3.13 IC3.15 ICSP.4 ICSP.9 ICSP.10 J1.1 J1.9 J1.10 J1.11 RS232IC.7 RS232IC.8 RS232IC.9 RS232IC.10 Swich.10
copper on no net: | length 60.9
  Top Layer w0.254: 22.355,27.179 22.86,25.654 ; 22.476,94.87 22.987,96.393 ; 22.606,25.654 23.114,25.654 ; 22.733,96.393 23.241,96.393 ; 22.908,52.365 22.86,25.654 ; 22.939,69.682 22.987,96.393 ; 23.371,27.177 22.86,25.654 ; 23.492,94.868 22.987,96.393

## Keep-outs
Keep-Out Layer:
  lines w0.254: 25.654,86.36 25.781,25.781 ; 25.908,86.233 177.546,86.233 177.673,86.36 177.927,25.527 26.035,25.527 ; 32.385,25.781 32.639,25.527

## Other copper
Top Layer:
  text "70.7391 (mm)" at 23.823,52.617 h1.52 r89.9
